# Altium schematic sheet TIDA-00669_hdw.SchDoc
size 431 x 279 mm; Date: Not shown in title block; ApprovedBy: Not shown in title block; CheckedBy: Not shown in title block; Author: Not shown in title block; CompanyName: Not shown in title block; Engineer: Not shown in title block; Organization: Not shown in title block; Address1: Not shown in title block; Address2: Not shown in title block; Address3: Not shown in title block; Address4: Not shown in title block; DocumentNumber: 1; Revision: Use project parameter SCH_Rev; SheetNumber: 3; SheetTotal: 3; PageSetup: Record=PageOptions¦CenterHorizontal=True¦CenterVertical=True¦PrintScale=1.00¦XCorrection=1.00¦YCorrection=1.00¦PrintKind=0¦BorderSize=5000000¦LeftOffset=0¦BottomOffset=0¦Orientation=2¦PaperLength=1000¦PaperWidth=1000¦Scale=100¦PaperSource=15¦PrintQuality=600¦MediaType=1¦DitherType=10¦PaperKind=Letter¦PrintScaleMode=1
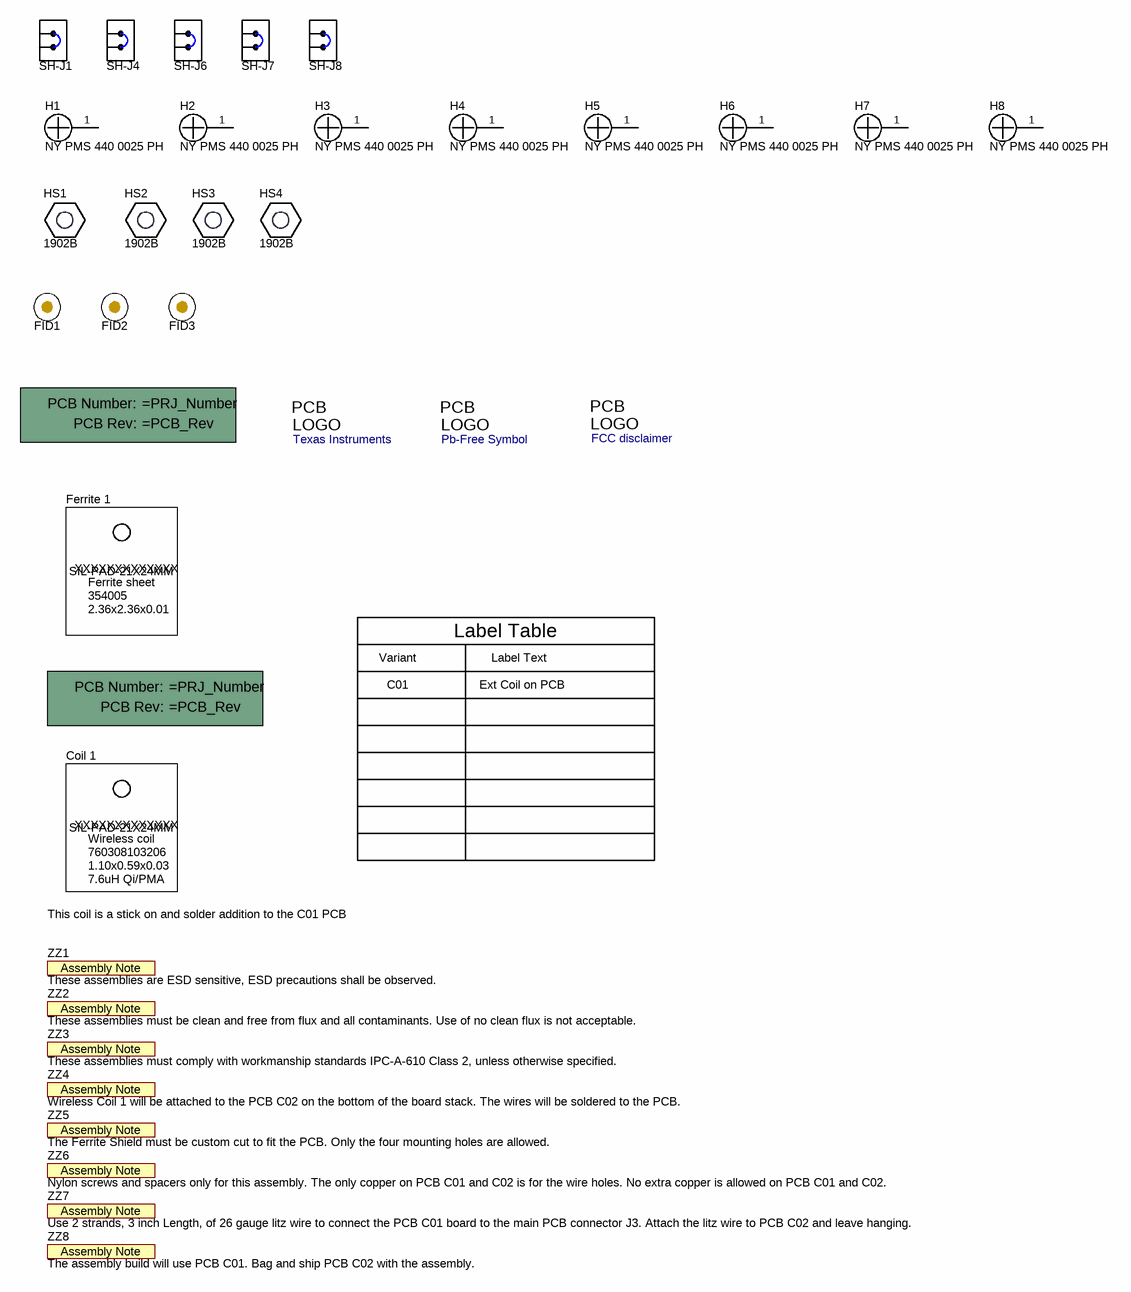
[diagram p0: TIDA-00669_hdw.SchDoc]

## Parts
!PCB1  Printed Circuit Board  (value not drawn)  (mechanical)
!PCB2  Printed Circuit Board  (value not drawn)  (mechanical)
Coil_1  value 7.6uH Qi/PMA  PackageReference: 1.10x0.59x0.03  Mask: XXXXXXXXXXXXX  [SIL-PAD_24X21MM]  (hidden comment: 760308103206)
Ferrite_1  CompType: Ferrite sheet  PackageReference: 2.36x2.36x0.01  Mask: XXXXXXXXXXXXX  [SIL-PAD_24X21MM]  (hidden comment: 354005)
FID1  Fiducial  [Fiducial10-20]  (value not drawn)
FID2  Fiducial  [Fiducial10-20]  (value not drawn)
FID3  Fiducial  [Fiducial10-20]  (value not drawn)
H1  NY PMS 440 0025 PH  [NY PMS 440 0025 PH]
H2  NY PMS 440 0025 PH  [NY PMS 440 0025 PH]
H3  NY PMS 440 0025 PH  [NY PMS 440 0025 PH]
H4  NY PMS 440 0025 PH  [NY PMS 440 0025 PH]
H5  NY PMS 440 0025 PH  [NY PMS 440 0025 PH]
H6  NY PMS 440 0025 PH  [NY PMS 440 0025 PH]
H7  NY PMS 440 0025 PH  [NY PMS 440 0025 PH]
H8  NY PMS 440 0025 PH  [NY PMS 440 0025 PH]
HS1  1902B  [Keystone_1902B]
HS2  1902B  [Keystone_1902B]
HS3  1902B  [Keystone_1902B]
HS4  1902B  [Keystone_1902B]
Logo1  Texas Instruments  [TI_Symbol_Overlay_Small]  (no BOM)
Logo2  Pb-Free Symbol  [Pb-Free_Overlay_Small]  (no BOM)
Logo3  FCC disclaimer  [FCC_disclaimer]  (no BOM)
SH-J1  969102-0000-DA  [SNT-100-BK-G]  (value not drawn)
SH-J4  969102-0000-DA  [SNT-100-BK-G]  (value not drawn)
SH-J6  969102-0000-DA  [SNT-100-BK-G]  (value not drawn)
SH-J7  969102-0000-DA  [SNT-100-BK-G]  (value not drawn)
SH-J8  969102-0000-DA  [SNT-100-BK-G]  (value not drawn)
ZZ1  These assemblies are ESD sensitive, ESD precautions shall be observed.  [AssemblyNote]  (no BOM)
ZZ2  These assemblies must be clean and free from flux and all contaminants. Use of no clean flux is not acceptable.  [AssemblyNote]  (no BOM)
ZZ3  These assemblies must comply with workmanship standards IPC-A-610 Class 2, unless otherwise specified.  [AssemblyNote]  (no BOM)
ZZ4  Wireless Coil 1 will be attached to the PCB C02 on the bottom of the board stack. The wires will be soldered to the PCB.  [AssemblyNote]  (no BOM)
ZZ5  The Ferrite Shield must be custom cut to fit the PCB. Only the four mounting holes are allowed.  [AssemblyNote]  (no BOM)
ZZ6  Nylon screws and spacers only for this assembly. The only copper on PCB C01 and C02 is for the wire holes. No extra copper is allowed on PCB C01 and C02.  [AssemblyNote]  (no BOM)
ZZ7  Use 2 strands, 3 inch Length, of 26 gauge litz wire to connect the PCB C01 board to the main PCB connector J3. Attach the litz wire to PCB C02 and leave hanging.  [AssemblyNote]  (no BOM)
ZZ8  The assembly build will use PCB C01. Bag and ship PCB C02 with the assembly.  [AssemblyNote]  (no BOM)

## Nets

Not connected (* = marked no-connect by the designer): H1 1; H2 1; H3 1; H4 1; H5 1; H6 1; H7 1; H8 1

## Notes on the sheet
- Variant
- Label Table
- Label Text
- C01
- Ext Coil on PCB
- (near ZZ1) This coil is a stick on and solder addition to the C01 PCB

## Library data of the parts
!PCB1 !PCB2 = PCB: Manufacturer: Any; SymbolCreator: a0412235
Coil_1 = SP900S-0.009-00-114: Wireless coil; Manufacturer: Wurth; SymbolCreator: a0799628
Ferrite_1 = SP900S-0.009-00-114: Ferrite shield; Manufacturer: Wurth; SymbolCreator: a0799628; Value: WE-FSFS
FID1-FID3 = Fiducial: Fiducial mark.  There is nothing to buy or mount.; SymbolCreator: codlsc
H1-H8 = NY PMS 440 0025 PH: Machine Screw, Round, #4-40 x 1/4, Nylon, Philips panhead; Manufacturer: B&F Fastener Supply; CompType: Hardware; SymbolCreator: codlsc; U/M: EA
HS1-HS4 = 1902B: Standoff, Hex, 0.375"L #4-40 Nylon; Manufacturer: Keystone; SymbolCreator: a0412235; CompType: Hardware
Logo1 = TI_Logo: Texas Instrument Corporate Signature; SymbolCreator: a0412235
Logo2 = Pb-Free: SymbolCreator: a0412235
Logo3 = FCC_disclaimer: SymbolCreator: codlsc
SH-J1 SH-J4 SH-J6-SH-J8 = 969102-0000-DA: Shunt, 100mil, Gold plated, Black; Manufacturer: 3M; Alternate Manufacturer: Samtec; Value: 1x2; Note: You can "mate" this to a header by matching the designator.  i.e. use SH-J3 for header J3
ZZ1-ZZ8 = AssemblyNote: SymbolCreator: codlsc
